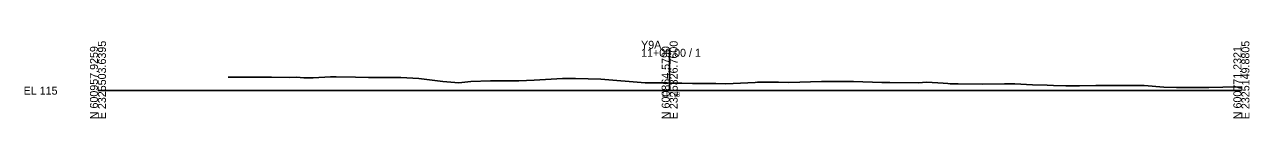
# Model space of a CAD drawing. Extents: x -26 to 2325310, y -10 to 600913.
# Drawn here: x -25.7 to 402.8, y 1990.3 to 2017.5 of the extents above; entities that cross this region are included whole.
import ezdxf

# ---------------------------------------------------------------- set-up
doc = ezdxf.new("R2010")
doc.units = 0
for name, color, linetype in [('Default', 7, 'Continuous'), ('Exist Cross Section Cell', 7, 'Continuous'), ('Exist XS Center Line Elevation Label', 7, 'Continuous'), ('Exist XS Ground Line', 7, 'Continuous')]:
    doc.layers.add(name, color=color, linetype=linetype)

msp = doc.modelspace()

# ---------------------------------------------------------------- linework, layer by layer
at = {"layer": 'Exist Cross Section Cell'}
for p, q in [((200, 2000), (200, 2014.67)), ((0, 2000), (200, 2000)), ((200, 2000), (400, 2000))]:
    msp.add_line(p, q, dxfattribs=at)
at = {"layer": 'Exist XS Ground Line'}
msp.add_lwpolyline([(45.61, 2004.72), (56.64, 2004.78), (60.71, 2004.74), (67.01, 2004.61), (69.5, 2004.76), (72.01, 2004.54), (75.26, 2004.51), (81.4, 2004.82), (82.66, 2004.89), (83.32, 2004.89), (90.06, 2004.76), (94.63, 2004.63), (97.46, 2004.56), (102.83, 2004.62), (104.86, 2004.65), (105.94, 2004.61), (112.27, 2004.23), (120.7, 2003.17), (126.28, 2002.74), (130.45, 2003.18), (137.3, 2003.39), (139.95, 2003.41), (143.72, 2003.4), (147.25, 2003.39), (152.55, 2003.67), (162.48, 2004.26), (164.08, 2004.25), (167.11, 2004.24), (171.48, 2004.16), (175.94, 2003.98), (191.43, 2002.77), (195.13, 2002.72), (199.16, 2002.69), (200, 2002.68), (204.28, 2002.61), (208.02, 2002.52), (216.15, 2002.51), (219.63, 2002.35), (229.88, 2002.9), (230.7, 2002.94), (231.4, 2002.92), (238.1, 2002.95), (241.64, 2002.91), (253.09, 2003.19), (264.26, 2003.18), (274.25, 2002.88), (275.57, 2002.89), (277.04, 2002.88), (286.88, 2002.79), (289.92, 2003.01), (295.68, 2002.58), (297.32, 2002.51), (298.18, 2002.44), (300.98, 2002.42), (309.49, 2002.3), (317.11, 2002.38), (319.53, 2002.36), (320.8, 2002.35), (326.93, 2002.01), (332.11, 2001.9), (334.33, 2001.76), (338.54, 2001.73), (341.73, 2001.69), (343.42, 2001.72), (349.13, 2001.77), (354.73, 2001.85), (356.54, 2001.83), (359.96, 2001.76), (366.04, 2001.76), (372.82, 2001.27), (377.34, 2001.1), (378.74, 2001.09), (381.39, 2001.09), (386.15, 2001.08), (388.65, 2001.13), (393.55, 2001.26), (400, 2001.3)], dxfattribs=at)

# ---------------------------------------------------------------- texts
at = {"layer": 'Default'}
msp.add_text('-', height=0.0001, dxfattribs=at).set_placement((0, 2000))
msp.add_text('-', height=0.0001, dxfattribs=at).set_placement((0, 2000))
at = {"layer": 'Exist Cross Section Cell'}
for s, p in [('N 600957.9259', (0, 1990)), ('E 2325503.6395', (2.8, 1990)), ('N 600864.5790', (200, 1990)), ('E 2325326.7600', (202.8, 1990)), ('N 600771.2321', (400, 1990)), ('E 2325149.8805', (402.8, 1990))]:
    msp.add_text(s, height=2.8, rotation=90, dxfattribs=at).set_placement(p)
for s, p in [('Y9A', (190, 2014.67)), ('11+00.00 / 1', (190, 2011.87)), ('EL 115', (-26, 1998.6))]:
    msp.add_text(s, height=2.8, dxfattribs=at).set_placement(p)
at = {"layer": 'Exist XS Center Line Elevation Label'}
msp.add_text('117.68', height=1.5, dxfattribs=at).set_placement((197.33, 1997.93))

doc.saveas('drawing.dxf')
